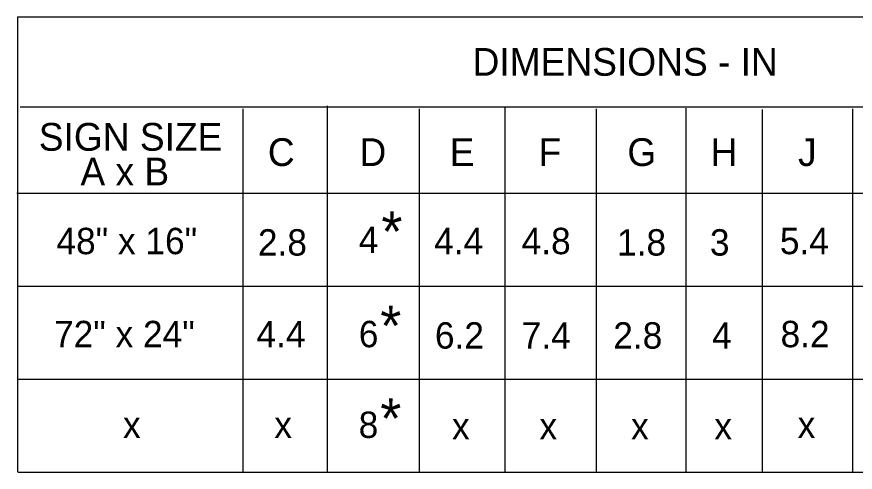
# Model space of a CAD drawing. Extents: x 0.013 to 0.187, y -0.092 to 0.261.
# Drawn here: x 0.031 to 0.1065, y -0.0502 to -0.0092 of the extents above; entities that cross this region are included whole.
import ezdxf

# ---------------------------------------------------------------- set-up
doc = ezdxf.new("R2010")
doc.units = 0
doc.layers.add('2', color=7, linetype='Continuous')
doc.layers.add('3', color=7, linetype='Continuous')

msp = doc.modelspace()

# ---------------------------------------------------------------- linework, layer by layer
at = {"layer": '3'}
for p, q in [((0.031089, -0.009213), (0.031089, -0.050213)), ((0.031089, -0.009213), (0.140321, -0.009213)), ((0.140321, -0.017338), (0.031321, -0.017338)), ((0.058969, -0.017239), (0.058969, -0.050213)), ((0.074962, -0.017307), (0.074962, -0.050213)), ((0.051383, -0.017489), (0.051383, -0.050213)), ((0.06725, -0.017489), (0.06725, -0.050213)), ((0.083185, -0.017489), (0.083185, -0.050213)), ((0.091276, -0.017428), (0.091276, -0.050213)), ((0.098155, -0.01755), (0.098155, -0.050213)), ((0.106276, -0.017489), (0.106276, -0.050213)), ((0.031022, -0.025088), (0.140321, -0.025088)), ((0.031089, -0.033463), (0.140321, -0.033463)), ((0.031156, -0.041838), (0.140321, -0.041838)), ((0.031156, -0.050213), (0.140321, -0.050213))]:
    msp.add_line(p, q, dxfattribs=at)

# ---------------------------------------------------------------- texts
at = {"layer": '2'}
for p in [(0.063855, -0.030367), (0.063752, -0.038854), (0.063752, -0.047195)]:
    msp.add_text('*', height=0.003645, dxfattribs=at).set_placement(p)
at = {"layer": '3'}
for s, height, p in [('DIMENSIONS - IN', 0.00249975, (0.072068, -0.014523)), ('SIGN SIZE', 0.0024998, (0.033006, -0.021273)), ('C', 0.0025, (0.053631, -0.022648)), ('D', 0.0025, (0.061881, -0.022648)), ('E', 0.0025, (0.070006, -0.022648)), ('F', 0.0025, (0.078006, -0.022648)), ('G', 0.0025, (0.086006, -0.022648)), ('H', 0.0025, (0.093506, -0.022648)), ('J', 0.0025, (0.101381, -0.022648)), ('A x B', 0.0024998, (0.036756, -0.024398)), ('48" x 16"', 0.0023752, (0.034593, -0.030586)), ('2.8', 0.0023752, (0.052737, -0.030711)), ('4', 0.002375, (0.061812, -0.030483)), ('4.4', 0.0023752, (0.068613, -0.030586)), ('4.8', 0.0023752, (0.076487, -0.030586)), ('1.8', 0.0023752, (0.085078, -0.030711)), ('3', 0.002375, (0.093438, -0.030711)), ('5.4', 0.0023752, (0.099738, -0.030586)), ('72" x 24"', 0.0023752, (0.034377, -0.038961)), ('4.4', 0.0023752, (0.052613, -0.038961)), ('6', 0.002375, (0.061823, -0.038961)), ('6.2', 0.0023752, (0.068676, -0.039086)), ('7.4', 0.0023752, (0.076488, -0.039086)), ('2.8', 0.0023752, (0.084737, -0.039086)), ('4', 0.002375, (0.093642, -0.039086)), ('8.2', 0.0023752, (0.099801, -0.038961)), ('8', 0.002375, (0.06181, -0.047127)), ('x', 0.002375, (0.040591, -0.047127)), ('x', 0.002375, (0.054216, -0.047127)), ('x', 0.002375, (0.070216, -0.047252)), ('x', 0.002375, (0.078091, -0.047252)), ('x', 0.002375, (0.086341, -0.047252)), ('x', 0.002375, (0.093841, -0.047252)), ('x', 0.002375, (0.101341, -0.047127))]:
    msp.add_text(s, height=height, dxfattribs=at).set_placement(p)

doc.saveas('drawing.dxf')
